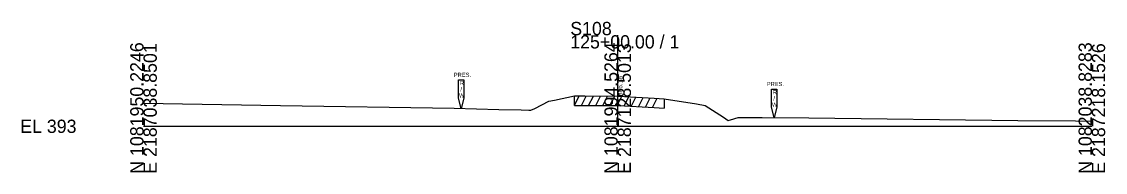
# Model space of a CAD drawing. Extents: x -26 to 2203, y 490 to 19581.
# Drawn here: x 1974.3 to 2202.8, y 3490.3 to 3522 of the extents above; entities that cross this region are included whole.
import ezdxf

# ---------------------------------------------------------------- set-up
doc = ezdxf.new("R2010")
doc.units = 0
for name, color, linetype in [('RD_GPK_XS_Cell', 7, 'Continuous'), ('RD_XS_ExGround', 7, 'Continuous'), ('RD_XS_ExPaveRet', 7, 'Continuous'), ('RD_XS_ExRW', 7, 'Continuous'), ('RD_XS_TX_Elev_EX', 7, 'Continuous')]:
    doc.layers.add(name, color=color, linetype=linetype)

msp = doc.modelspace()

# ---------------------------------------------------------------- linework, layer by layer
at = {"layer": 'RD_GPK_XS_Cell'}
for p, q in [((2100, 3500), (2100, 3519.19)), ((2000, 3500), (2100, 3500)), ((2100, 3500), (2200, 3500))]:
    msp.add_line(p, q, dxfattribs=at)
at = {"layer": 'RD_XS_ExGround'}
msp.add_lwpolyline([(2000, 3504.88), (2028.92, 3504.38), (2065.51, 3503.79), (2074.92, 3503.56), (2079.64, 3503.44), (2081.27, 3503.41), (2081.68, 3503.41), (2082.5, 3503.78), (2085.49, 3505.27), (2086.67, 3505.51), (2090.87, 3506.4), (2093.07, 3506.39), (2100.16, 3506.36), (2107.66, 3505.93), (2109.83, 3505.8), (2116.63, 3504.7), (2118.42, 3504.4), (2122.31, 3501.9), (2123.31, 3501.22), (2123.76, 3501.36), (2125.41, 3501.85), (2130.49, 3501.84), (2140.33, 3501.81), (2184.41, 3501.23), (2196.57, 3501.14), (2200, 3501.07)], dxfattribs=at)
at = {"layer": 'RD_XS_ExPaveRet'}
for p, q in [((2090.87, 3504.4), (2090.87, 3506.4)), ((2090.87, 3504.4), (2091.87, 3506.39)), ((2092.37, 3504.39), (2093.37, 3506.38)), ((2093.87, 3504.38), (2094.87, 3506.38)), ((2095.37, 3504.38), (2096.37, 3506.37)), ((2096.87, 3504.37), (2097.87, 3506.37)), ((2098.37, 3504.37), (2099.37, 3506.36)), ((2099.87, 3504.36), (2100.85, 3506.32)), ((2101.37, 3504.29), (2102.34, 3506.23)), ((2102.87, 3504.2), (2103.84, 3506.15)), ((2104.37, 3504.12), (2105.34, 3506.06)), ((2105.87, 3504.03), (2106.84, 3505.97)), ((2107.37, 3503.94), (2108.34, 3505.89)), ((2109.83, 3505.8), (2109.83, 3503.8)), ((2090.87, 3504.4), (2093.07, 3504.39)), ((2093.07, 3504.39), (2100.16, 3504.36)), ((2100.16, 3504.36), (2107.66, 3503.93)), ((2107.66, 3503.93), (2109.83, 3503.8))]:
    msp.add_line(p, q, dxfattribs=at)
at = {"layer": 'RD_XS_ExRW'}
for points in [[(2066.45, 3509.77), (2067.55, 3509.77), (2067.55, 3505.94), (2067, 3503.76), (2066.45, 3505.94)], [(2132.45, 3507.85), (2133.55, 3507.85), (2133.55, 3504.02), (2133, 3501.83), (2132.45, 3504.02)]]:
    msp.add_lwpolyline(points, close=True, dxfattribs=at)

# ---------------------------------------------------------------- texts
at = {"layer": 'RD_GPK_XS_Cell'}
for s, p in [('S108', (2090, 3519.19)), ('125+00.00 / 1', (2090, 3516.39)), ('EL 393', (1974, 3498.6))]:
    msp.add_text(s, height=2.8, dxfattribs=at).set_placement(p)
for s, p in [('N 1081950.2246', (2000, 3490)), ('E 2187038.8501', (2002.8, 3490)), ('N 1081994.5264', (2100, 3490)), ('E 2187128.5013', (2102.8, 3490)), ('N 1082038.8283', (2200, 3490)), ('E 2187218.1526', (2202.8, 3490))]:
    msp.add_text(s, height=2.8, rotation=90, dxfattribs=at).set_placement(p)
at = {"layer": 'RD_XS_ExRW'}
for s, p in [('PRES.', (2065.45, 3510.4)), ('R', (2066.71, 3508.68)), ('/', (2066.83, 3507.37)), ('PRES.', (2131.45, 3508.47)), ('W', (2066.53, 3506.06)), ('R', (2132.71, 3506.75)), ('/', (2132.83, 3505.44)), ('W', (2132.53, 3504.13))]:
    msp.add_text(s, height=0.875, dxfattribs=at).set_placement(p)
at = {"layer": 'RD_XS_TX_Elev_EX'}
msp.add_text('396.18', height=1, rotation=90, dxfattribs=at).set_placement((2101, 3506.36))

doc.saveas('drawing.dxf')
